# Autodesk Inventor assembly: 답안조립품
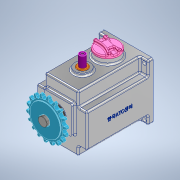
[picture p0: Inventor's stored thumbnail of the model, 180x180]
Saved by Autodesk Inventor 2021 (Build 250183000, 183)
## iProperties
Created: 2022-08
Part Number: 답안조립품
Document SubType Name: Assembly
Designer: Owner
Author: Owner
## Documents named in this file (16)
- C:\Users\Owner\Desktop\720810V1016\답안조립품.iam
- C:\Users\Owner\Desktop\720810V1016\본체.ipt
- C:\Users\Owner\Desktop\720810V1016\멈춤나사 M3.ipt
- C:\Users\Owner\Desktop\720810V1016\메인 축.ipt
- C:\Users\Owner\Desktop\720810V1016\베어링 608.ipt
- C:\Users\Owner\Desktop\720810V1016\베어링 6003.ipt
- C:\Users\Owner\Desktop\720810V1016\볼트 M4 x 10.ipt
- C:\Users\Owner\Desktop\720810V1016\부시.ipt
- C:\Users\Owner\Desktop\720810V1016\상부 캡.ipt
- C:\Users\Owner\Desktop\720810V1016\서브 축.ipt
- C:\Users\Owner\Desktop\720810V1016\스프로킷.ipt
- C:\Users\Owner\Desktop\720810V1016\슬라이더.ipt
- C:\Users\Owner\Desktop\720810V1016\오일 실 8 x 22 x 7.ipt
- C:\Users\Owner\Desktop\720810V1016\오일 실 17 x 32 x 8.ipt
- C:\Users\Owner\Desktop\720810V1016\커버.ipt
- C:\Users\Owner\Desktop\720810V1016\키 5 x 5.ipt
